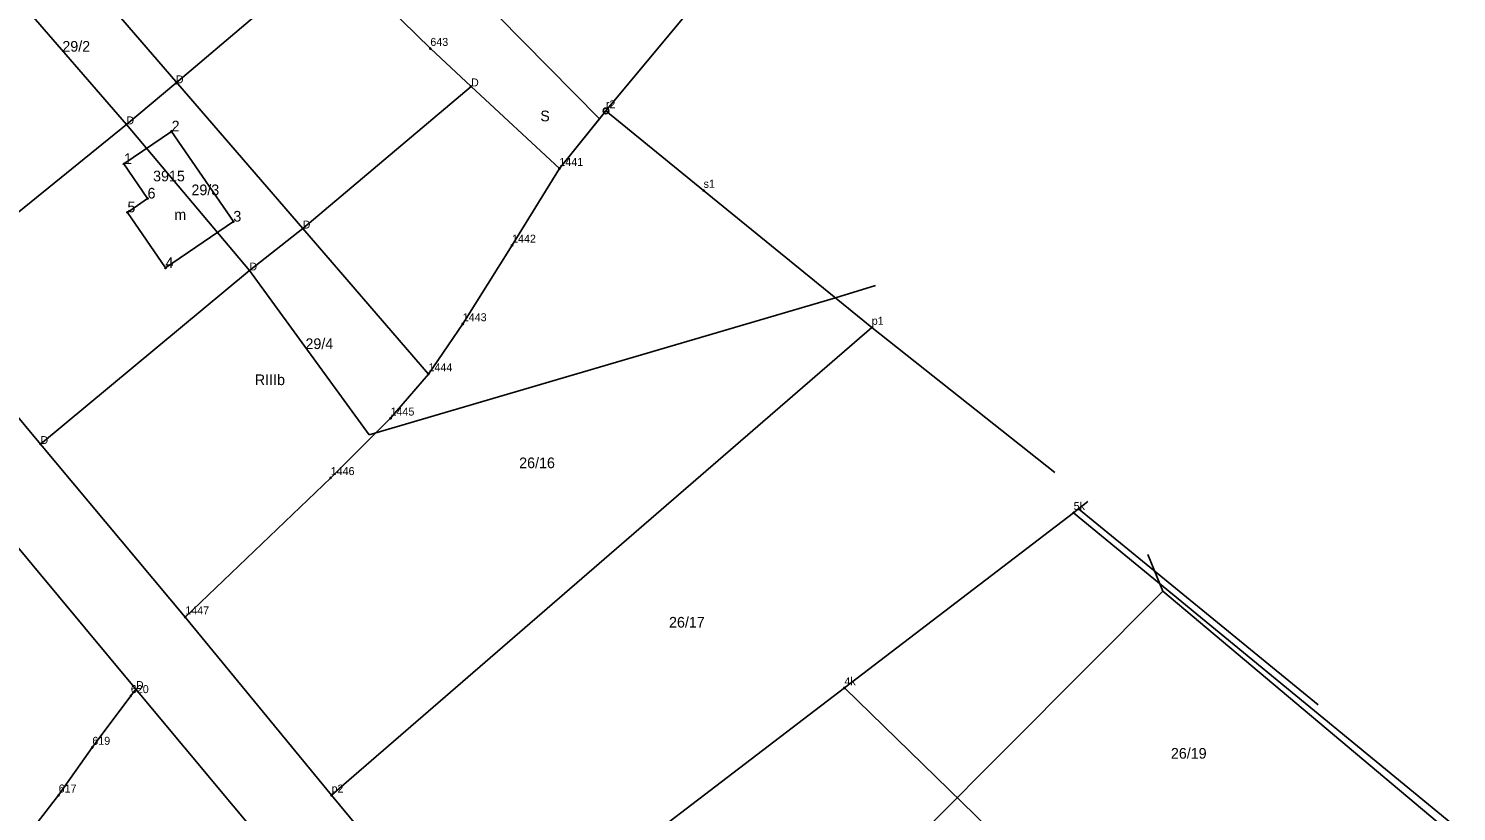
# Model space of a CAD drawing. Extents: x 7467189 to 7469366, y 5491487 to 5492734.
# Drawn here: x 7467609.4 to 7467810.1, y 5492141.7 to 5492251.8 of the extents above; entities that cross this region are included whole.
import ezdxf

# ---------------------------------------------------------------- set-up
doc = ezdxf.new("R2010")
doc.units = 0
for name, color, linetype in [('202-punkt graniczny', 7, 'Continuous'), ('202-punkt graniczny-Atr103', 7, 'Continuous'), ('203-punkt graniczny', 7, 'Continuous'), ('203-punkt graniczny-Atr103', 7, 'Continuous'), ('209-oznaczenie konturu klasyfikacyjnego', 7, 'Continuous'), ('210-oznaczenie konturu użytku gruntowego', 7, 'Continuous'), ('211-numer działki ewidencyjnej', 7, 'Continuous'), ('217-kontur klasyfikacyjny', 7, 'Continuous'), ('218-kontur użytku gruntowego', 7, 'Continuous'), ('219-działka ewidencyjna', 7, 'Continuous'), ('312-budynek ewidencyjny', 7, 'Continuous'), ('312-oznaczenie budynku ewidencyjnego', 7, 'Continuous'), ('312-oznaczenie budynku ewidencyjnego-Atr117', 7, 'Continuous'), ('Punkt budynku', 7, 'Continuous'), ('Punkt budynku-Atr104', 7, 'Continuous')]:
    doc.layers.add(name, color=color, linetype=linetype)

# ---------------------------------------------------------------- blocks, each defined once
blk = doc.blocks.new('203')
blk.add_circle((0, 0), 0.09)
blk = doc.blocks.new('202')
blk.add_circle((0, 0), 0.4)
blk = doc.blocks.new('PUNKTBUD')
blk.add_circle((0, 0), 0.09)

msp = doc.modelspace()

# ---------------------------------------------------------------- linework, layer by layer
at = {"layer": '217-kontur klasyfikacyjny'}
for points in [[(7467621.64, 5492308.06), (7467689.65, 5492239.08)], [(7467605.46, 5492258.76), (7467623.13, 5492238.31)], [(7467690.56, 5492240.21), (7467702.46, 5492254.52)], [(7467689.65, 5492239.08), (7467690.56, 5492240.21)], [(7467623.13, 5492238.31), (7467640.43, 5492217.76)], [(7467624.48, 5492158.89), (7467562.88, 5492232.89)], [(7467640.43, 5492217.76), (7467657.29, 5492194.66)], [(7467722.82, 5492213.91), (7467728.45, 5492215.63)], [(7467593.57, 5492214.35), (7467611.05, 5492193.35)], [(7467657.29, 5492194.66), (7467722.82, 5492213.91)], [(7467611.05, 5492193.35), (7467631.41, 5492169)], [(7467766.73, 5492177.81), (7467768.85, 5492172.64)], [(7467768.85, 5492172.64), (7467713.9, 5492117.44)], [(7467768.85, 5492172.64), (7467809.48, 5492138.48)], [(7467631.41, 5492169), (7467651.98, 5492143.94)], [(7467665.5, 5492109.62), (7467624.48, 5492158.89)], [(7467651.98, 5492143.94), (7467672.25, 5492119.45)]]:
    msp.add_lwpolyline(points, dxfattribs=at)
at = {"layer": '218-kontur użytku gruntowego'}
for points in [[(7467689.65, 5492239.08), (7467621.64, 5492308.06)], [(7467595.49, 5492284.39), (7467647.92, 5492223.66)], [(7467684.01, 5492232.09), (7467689.65, 5492239.08)], [(7467624.48, 5492158.89), (7467562.88, 5492232.89)], [(7467677.36, 5492221.3), (7467684.01, 5492232.09)], [(7467647.92, 5492223.66), (7467665.61, 5492203.19)], [(7467670.43, 5492210.24), (7467677.36, 5492221.3)], [(7467593.57, 5492214.35), (7467611.05, 5492193.35)], [(7467665.61, 5492203.19), (7467670.43, 5492210.24)], [(7467611.05, 5492193.35), (7467631.41, 5492169)], [(7467631.41, 5492169), (7467651.98, 5492143.94)], [(7467665.5, 5492109.62), (7467624.48, 5492158.89)], [(7467651.98, 5492143.94), (7467672.25, 5492119.45)]]:
    msp.add_lwpolyline(points, dxfattribs=at)
at = {"layer": '219-działka ewidencyjna'}
for points in [[(7467630.09, 5492244.09), (7467651.91, 5492262.69)], [(7467651.91, 5492262.69), (7467665.87, 5492248.97)], [(7467702.46, 5492254.52), (7467690.56, 5492240.21)], [(7467671.59, 5492243.65), (7467665.87, 5492248.97)], [(7467623.13, 5492238.31), (7467630.09, 5492244.09)], [(7467647.92, 5492223.66), (7467671.59, 5492243.65)], [(7467671.59, 5492243.65), (7467684.01, 5492232.09)], [(7467690.56, 5492240.21), (7467684.01, 5492232.09)], [(7467690.56, 5492240.21), (7467704.29, 5492229.01)], [(7467593.57, 5492214.35), (7467623.13, 5492238.31)], [(7467624.48, 5492158.89), (7467562.88, 5492232.89)], [(7467677.36, 5492221.3), (7467684.01, 5492232.09)], [(7467704.29, 5492229.01), (7467727.93, 5492209.74)], [(7467640.43, 5492217.76), (7467647.92, 5492223.66)], [(7467670.43, 5492210.24), (7467677.36, 5492221.3)], [(7467611.05, 5492193.35), (7467640.43, 5492217.76)], [(7467593.57, 5492214.35), (7467611.05, 5492193.35)], [(7467651.98, 5492143.94), (7467727.93, 5492209.74)], [(7467665.61, 5492203.19), (7467670.43, 5492210.24)], [(7467727.93, 5492209.74), (7467753.67, 5492189.35)], [(7467665.61, 5492203.19), (7467660.28, 5492196.98)], [(7467651.86, 5492188.6), (7467660.28, 5492196.98)], [(7467611.05, 5492193.35), (7467631.41, 5492169)], [(7467631.41, 5492169), (7467651.86, 5492188.6)], [(7467757, 5492184.21), (7467758.3, 5492185.27)], [(7467724.09, 5492159.04), (7467756.32, 5492183.69)], [(7467756.32, 5492183.69), (7467757, 5492184.21)], [(7467756.32, 5492183.69), (7467810.14, 5492139.39)], [(7467757, 5492184.21), (7467790.68, 5492156.67)], [(7467651.98, 5492143.94), (7467631.41, 5492169)], [(7467624.48, 5492158.89), (7467623.76, 5492157.93)], [(7467624.48, 5492158.89), (7467665.5, 5492109.62)], [(7467694.46, 5492136.39), (7467724.09, 5492159.04)], [(7467724.09, 5492159.04), (7467782.84, 5492101.79)], [(7467618.34, 5492150.67), (7467623.76, 5492157.93)], [(7467613.61, 5492143.95), (7467618.34, 5492150.67)], [(7467613.61, 5492143.95), (7467605.35, 5492133.29)], [(7467651.98, 5492143.94), (7467672.25, 5492119.45)]]:
    msp.add_lwpolyline(points, dxfattribs=at)
at = {"layer": '312-budynek ewidencyjny'}
for points in [[(7467622.79, 5492232.74), (7467629.49, 5492237.32)], [(7467629.49, 5492237.32), (7467638.17, 5492224.64)], [(7467626.11, 5492227.88), (7467622.79, 5492232.74)], [(7467623.28, 5492225.94), (7467626.11, 5492227.88)], [(7467628.63, 5492218.12), (7467623.28, 5492225.94)], [(7467638.17, 5492224.64), (7467628.63, 5492218.12)]]:
    msp.add_lwpolyline(points, dxfattribs=at)

# ---------------------------------------------------------------- block references
at = {"layer": '202-punkt graniczny'}
msp.add_blockref('202', (7467690.56, 5492240.21), dxfattribs=at)
at = {"layer": '203-punkt graniczny'}
for p in [(7467665.87, 5492248.97), (7467630.09, 5492244.09), (7467671.59, 5492243.65), (7467623.13, 5492238.31), (7467684.01, 5492232.09), (7467704.29, 5492229.01), (7467647.92, 5492223.66), (7467677.36, 5492221.3), (7467640.43, 5492217.76), (7467670.43, 5492210.24), (7467727.93, 5492209.74), (7467665.61, 5492203.19), (7467660.28, 5492196.98), (7467611.05, 5492193.35), (7467651.86, 5492188.6), (7467756.32, 5492183.69), (7467757, 5492184.21), (7467631.41, 5492169), (7467624.48, 5492158.89), (7467724.09, 5492159.04), (7467623.76, 5492157.93), (7467618.34, 5492150.67), (7467613.61, 5492143.95), (7467651.98, 5492143.94)]:
    msp.add_blockref('203', p, dxfattribs=at)
at = {"layer": 'Punkt budynku'}
for p in [(7467629.49, 5492237.32), (7467622.79, 5492232.74), (7467626.11, 5492227.88), (7467623.28, 5492225.94), (7467638.17, 5492224.64), (7467628.63, 5492218.12)]:
    msp.add_blockref('PUNKTBUD', p, dxfattribs=at)

# ---------------------------------------------------------------- texts
at = {"layer": '202-punkt graniczny-Atr103'}
msp.add_text('r2', height=1.125, dxfattribs=at).set_placement((7467690.56, 5492240.58))
at = {"layer": '203-punkt graniczny-Atr103'}
for s, height, p in [('643', 1.125, (7467665.87, 5492249.35)), ('D', 1.12, (7467630.09, 5492244.09)), ('D', 1.12, (7467671.59, 5492243.65)), ('D', 1.12, (7467623.13, 5492238.31)), ('1441', 1.125, (7467684.01, 5492232.46)), ('s1', 1.125, (7467704.29, 5492229.39)), ('D', 1.12, (7467647.92, 5492223.66)), ('1442', 1.125, (7467677.36, 5492221.67)), ('D', 1.12, (7467640.43, 5492217.76)), ('1443', 1.125, (7467670.43, 5492210.62)), ('p1', 1.125, (7467727.93, 5492210.12)), ('1444', 1.125, (7467665.61, 5492203.57)), ('1445', 1.125, (7467660.28, 5492197.36)), ('D', 1.12, (7467611.05, 5492193.35)), ('1446', 1.125, (7467651.86, 5492188.98)), ('5k', 1.125, (7467756.32, 5492184.07)), ('1447', 1.125, (7467631.41, 5492169.38)), ('4k', 1.125, (7467724.09, 5492159.42)), ('620', 1.125, (7467623.76, 5492158.31)), ('D', 1.12, (7467624.48, 5492158.89)), ('619', 1.125, (7467618.34, 5492151.04)), ('617', 1.125, (7467613.61, 5492144.33)), ('p2', 1.125, (7467651.98, 5492144.32))]:
    msp.add_text(s, height=height, dxfattribs=at).set_placement(p)
at = {"layer": '209-oznaczenie konturu klasyfikacyjnego'}
msp.add_text('RIIIb', height=1.5, dxfattribs=at).set_placement((7467641.19, 5492201.64))
at = {"layer": '210-oznaczenie konturu użytku gruntowego'}
msp.add_text('S', height=1.5, dxfattribs=at).set_placement((7467681.33, 5492238.75))
at = {"layer": '211-numer działki ewidencyjnej'}
for s, p in [('29/2', (7467614.13, 5492248.54)), ('29/3', (7467632.28, 5492228.35)), ('29/4', (7467648.31, 5492206.71)), ('26/16', (7467678.36, 5492189.95)), ('26/17', (7467699.43, 5492167.53)), ('26/19', (7467769.99, 5492149.09))]:
    msp.add_text(s, height=1.5, dxfattribs=at).set_placement(p)
at = {"layer": '312-oznaczenie budynku ewidencyjnego'}
msp.add_text('3915', height=1.5, dxfattribs=at).set_placement((7467626.89, 5492230.3))
at = {"layer": '312-oznaczenie budynku ewidencyjnego-Atr117'}
msp.add_text('m', height=1.5, dxfattribs=at).set_placement((7467629.87, 5492224.87))
at = {"layer": 'Punkt budynku-Atr104'}
for s, p in [('2', (7467629.49, 5492237.32)), ('1', (7467622.79, 5492232.74)), ('6', (7467626.11, 5492227.88)), ('5', (7467623.28, 5492225.94)), ('3', (7467638.17, 5492224.64)), ('4', (7467628.63, 5492218.12))]:
    msp.add_text(s, height=1.5, dxfattribs=at).set_placement(p)

doc.saveas('drawing.dxf')
